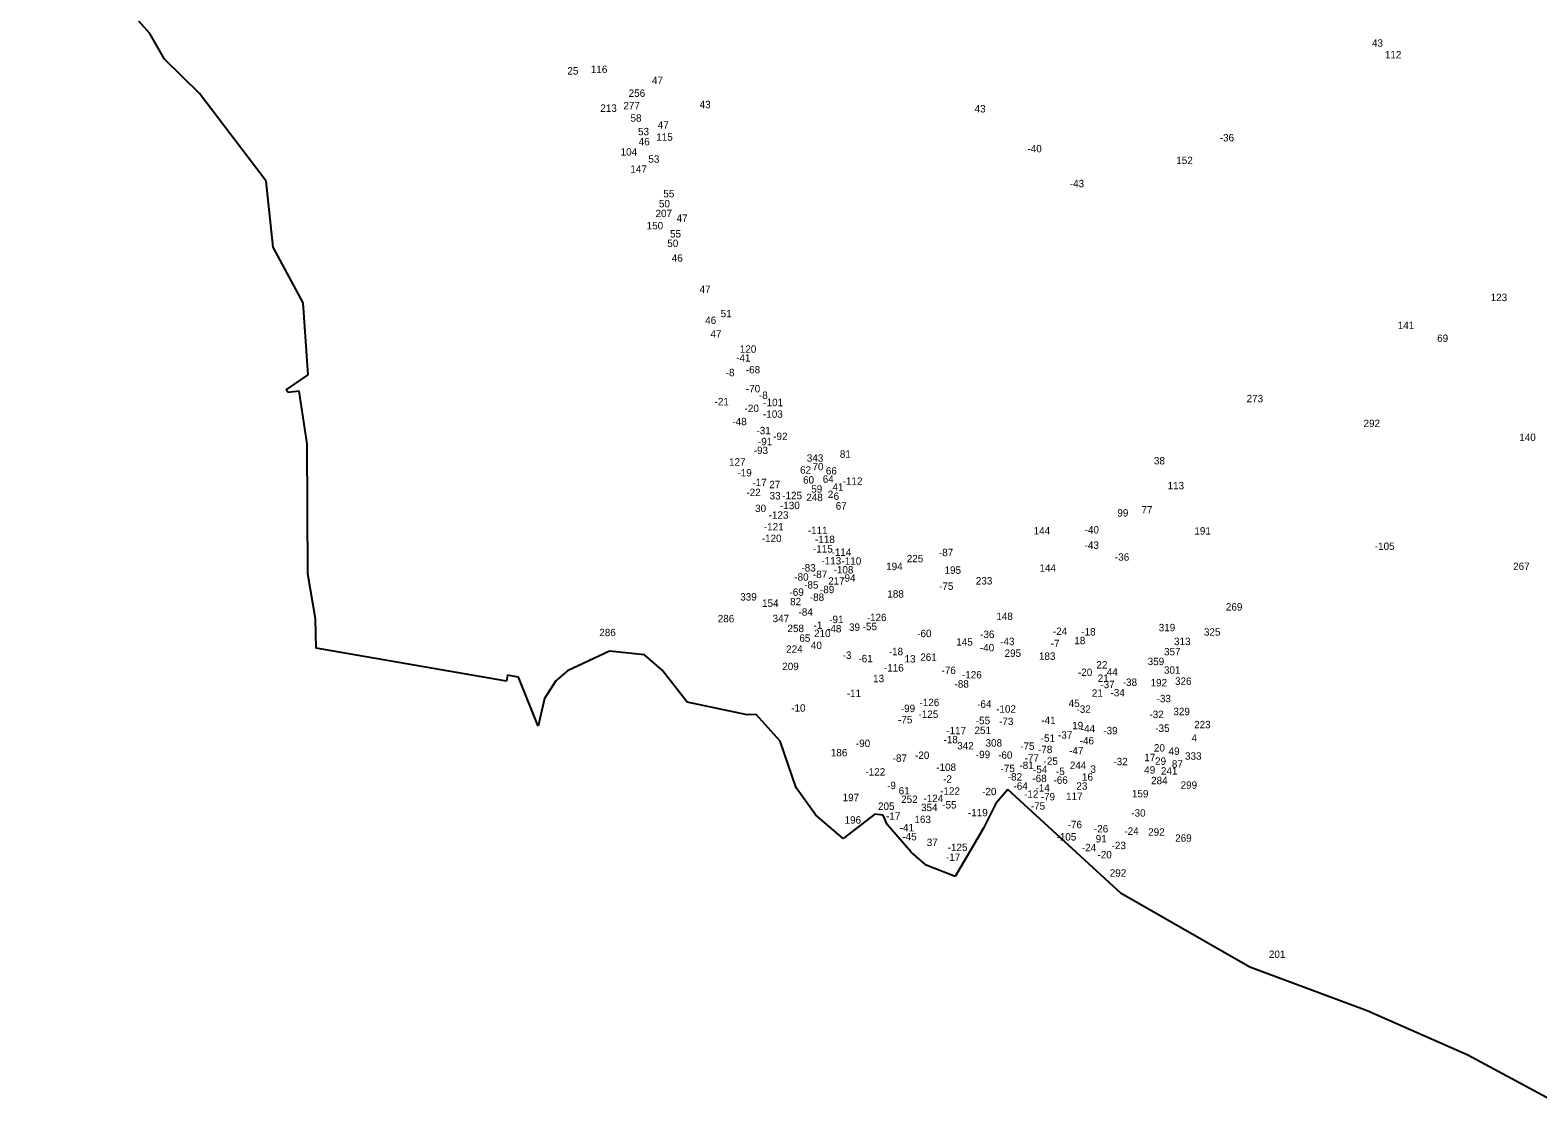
# Model space of a CAD drawing. Extents: x -780116 to -776974, y -980293 to -977147.
# Drawn here: x -779931 to -778640, y -979637 to -978721 of the extents above; entities that cross this region are included whole.
import ezdxf

# ---------------------------------------------------------------- set-up
doc = ezdxf.new("R2010")
doc.units = 0
doc.layers.add('Vrstva 15', color=7, linetype='Continuous')
doc.layers.add('Vrstva 24', color=7, linetype='Continuous')

msp = doc.modelspace()

# ---------------------------------------------------------------- linework, layer by layer
at = {"layer": 'Vrstva 15'}
for p, q in [((-779828.23, -978723.7), (-779930.79, -978608.31)), ((-779815.84, -978745.74), (-779828.23, -978723.7)), ((-779785.83, -978775.04), (-779815.84, -978745.74)), ((-779728.72, -978850.24), (-779785.83, -978775.04)), ((-779722.75, -978906.79), (-779728.72, -978850.24)), ((-779696.96, -978954.35), (-779722.75, -978906.79)), ((-779692.81, -979016.06), (-779696.96, -978954.35)), ((-779711.61, -979028.89), (-779692.81, -979016.06)), ((-779710, -979031.29), (-779711.61, -979028.89)), ((-779700.39, -979029.98), (-779710, -979031.29)), ((-779693.61, -979075.28), (-779700.39, -979029.98)), ((-779693.17, -979186.63), (-779693.61, -979075.28)), ((-779686.47, -979225.1), (-779693.17, -979186.63)), ((-779686.03, -979250.32), (-779686.47, -979225.1)), ((-779523.01, -979278.6), (-779686.03, -979250.32)), ((-779434.65, -979252.76), (-779470.71, -979269.6)), ((-779404.79, -979255.97), (-779434.65, -979252.76)), ((-779389.56, -979269.01), (-779404.79, -979255.97)), ((-779522.13, -979273.35), (-779523.01, -979278.6)), ((-779512.81, -979275.1), (-779522.13, -979273.35)), ((-779495.84, -979316.97), (-779512.81, -979275.1)), ((-779480.69, -979278.27), (-779490.52, -979293.36)), ((-779470.71, -979269.6), (-779480.69, -979278.27)), ((-779368.37, -979296.48), (-779389.56, -979269.01)), ((-779490.52, -979293.36), (-779495.84, -979316.97)), ((-779317.01, -979307.2), (-779368.37, -979296.48)), ((-779309.07, -979306.98), (-779317.01, -979307.2)), ((-779288.6, -979329.86), (-779309.07, -979306.98)), ((-779274.84, -979370.01), (-779288.6, -979329.86)), ((-779258.09, -979393.18), (-779274.84, -979370.01)), ((-779093.81, -979371.44), (-779103.95, -979383.43)), ((-778996.64, -979460.5), (-779093.81, -979371.44)), ((-779234.77, -979413.16), (-779258.09, -979393.18)), ((-779207.6, -979392.31), (-779234.77, -979413.16)), ((-779200.39, -979393.19), (-779207.6, -979392.31)), ((-779197.03, -979401.42), (-779200.39, -979393.19)), ((-779103.95, -979383.43), (-779114.58, -979404.42)), ((-779176.56, -979424.89), (-779197.03, -979401.42)), ((-779114.58, -979404.42), (-779138.91, -979445.95)), ((-779163.68, -979436.18), (-779176.56, -979424.89)), ((-779138.91, -979445.95), (-779163.68, -979436.18)), ((-778886.64, -979523.46), (-778996.64, -979460.5)), ((-778786.11, -979560.92), (-778886.64, -979523.46)), ((-778699.86, -979598.82), (-778786.11, -979560.92)), ((-778628.77, -979637.15), (-778699.86, -979598.82))]:
    msp.add_line(p, q, dxfattribs=at)

# ---------------------------------------------------------------- texts
at = {"layer": 'Vrstva 24'}
for s, p in [('43', (-778781.975, -978735.034)), ('112', (-778770.959, -978744.984)), ('25', (-779470.845, -978758.864)), ('116', (-779450.759, -978757.574)), ('47', (-779398.449, -978767.024)), ('256', (-779418.393, -978778.004)), ('213', (-779442.651, -978790.824)), ('277', (-779422.902, -978788.664)), ('43', (-779357.625, -978787.724)), ('43', (-779122.195, -978791.344)), ('58', (-779416.785, -978799.254)), ('47', (-779393.489, -978805.224)), ('53', (-779410.375, -978810.914)), ('46', (-779409.775, -978819.514)), ('115', (-779394.749, -978815.594)), ('-36', (-778912.299, -978816.154)), ('104', (-779425.245, -978828.304)), ('-40', (-779076.943, -978825.494)), ('147', (-779416.885, -978843.034)), ('53', (-779401.485, -978834.394)), ('152', (-778949.521, -978835.584)), ('-43', (-779040.678, -978855.384)), ('55', (-779388.695, -978864.074)), ('207', (-779395.393, -978881.034)), ('50', (-779392.48, -978872.664)), ('150', (-779402.956, -978891.474)), ('47', (-779377.319, -978885.054)), ('50', (-779385.28, -978906.634)), ('55', (-779382.975, -978898.464)), ('46', (-779381.505, -978919.244)), ('47', (-779357.649, -978946.004)), ('123', (-778680.361, -978952.954)), ('46', (-779352.865, -978972.534)), ('51', (-779339.633, -978966.784)), ('47', (-779348.319, -978984.204)), ('141', (-778759.908, -978976.864)), ('69', (-778726.155, -978987.924)), ('120', (-779323.226, -978997.184)), ('-41', (-779326.326, -979004.764)), ('-8', (-779335.301, -979017.294)), ('-68', (-779318.069, -979014.804)), ('-70', (-779317.998, -979031.134)), ('-8', (-779306.811, -979036.744)), ('273', (-778889.327, -979039.604)), ('-21', (-779344.827, -979042.214)), ('-20', (-779319.133, -979047.974)), ('-101', (-779303.097, -979042.944)), ('-48', (-779329.558, -979059.294)), ('-103', (-779303.349, -979052.884)), ('292', (-778789.203, -979060.824)), ('-31', (-779308.987, -979066.984)), ('-91', (-779307.667, -979076.394)), ('-92', (-779294.619, -979071.944)), ('140', (-778655.885, -979072.844)), ('-93', (-779311.299, -979083.964)), ('343', (-779265.843, -979090.544)), ('81', (-779237.543, -979087.164)), ('127', (-779332.446, -979093.884)), ('-19', (-779325.237, -979103.154)), ('62', (-779271.625, -979100.744)), ('70', (-779261.005, -979097.914)), ('66', (-779249.545, -979101.464)), ('38', (-778968.685, -979092.834)), ('-17', (-779312.441, -979111.464)), ('27', (-779297.96, -979113.224)), ('60', (-779269.05, -979109.284)), ('59', (-779262.075, -979117.084)), ('64', (-779252.235, -979108.564)), ('41', (-779243.882, -979115.354)), ('-112', (-779235.153, -979110.304)), ('113', (-778956.979, -979114.154)), ('-22', (-779317.569, -979119.924)), ('33', (-779297.715, -979122.844)), ('-125', (-779286.895, -979122.654)), ('248', (-779266.303, -979124.284)), ('2', (-779247.937, -979121.694)), ('-6', (-779245.761, -979123.204)), ('30', (-779310.13, -979133.644)), ('-123', (-779298.525, -979139.314)), ('-130', (-779288.819, -979131.154)), ('67', (-779241.11, -979131.514)), ('99', (-778999.985, -979137.494)), ('77', (-778979.344, -979134.864)), ('-121', (-779302.643, -979149.434)), ('-111', (-779264.991, -979152.494)), ('144', (-779071.64, -979152.794)), ('-40', (-779027.983, -979152.034)), ('191', (-778934.019, -979152.924)), ('-120', (-779304.429, -979159.344)), ('-115', (-779260.573, -979168.354)), ('-118', (-779258.823, -979160.194)), ('-43', (-779028.008, -979165.154)), ('-105', (-778779.579, -979166.074)), ('-113', (-779253.353, -979178.554)), ('-114', (-779244.693, -979171.194)), ('-110', (-779236.167, -979178.744)), ('225', (-779180.283, -979176.664)), ('-87', (-779152.763, -979171.414)), ('-36', (-779002.069, -979175.344)), ('-80', (-779276.563, -979192.424)), ('-83', (-779270.469, -979184.594)), ('-87', (-779260.623, -979190.164)), ('-108', (-779242.909, -979186.274)), ('-94', (-779236.399, -979193.264)), ('194', (-779197.921, -979183.404)), ('195', (-779147.941, -979186.534)), ('144', (-779066.66, -979184.734)), ('267', (-778661.128, -979183.324)), ('-69', (-779280.669, -979205.394)), ('-85', (-779268.139, -979199.204)), ('-89', (-779254.579, -979203.144)), ('217', (-779247.546, -979195.804)), ('188', (-779196.911, -979206.924)), ('-75', (-779152.623, -979200.274)), ('233', (-779121.153, -979195.704)), ('339', (-779322.853, -979209.454)), ('154', (-779304.171, -979214.854)), ('82', (-779280.175, -979213.514)), ('-88', (-779263.259, -979209.764)), ('269', (-778907.063, -979218.064)), ('286', (-779342.113, -979228.084)), ('347', (-779295.117, -979227.964)), ('-84', (-779272.959, -979222.414)), ('-91', (-779246.667, -979228.784)), ('-126', (-779214.545, -979227.064)), ('148', (-779103.56, -979226.094)), ('286', (-779443.533, -979239.954)), ('258', (-779282.393, -979236.474)), ('65', (-779272.245, -979244.754)), ('-1', (-779260.069, -979233.764)), ('210', (-779259.666, -979240.704)), ('-48', (-779248.478, -979236.734)), ('39', (-779229.745, -979235.394)), ('-55', (-779218.029, -979234.824)), ('-60', (-779171.363, -979240.804)), ('-36', (-779117.469, -979241.524)), ('-24', (-779055.119, -979238.904)), ('-18', (-779030.867, -979239.414)), ('319', (-778964.541, -979235.744)), ('325', (-778925.843, -979239.524)), ('224', (-779283.553, -979254.204)), ('40', (-779262.379, -979250.974)), ('-18', (-779195.667, -979256.254)), ('145', (-779137.92, -979248.064)), ('-40', (-779117.673, -979252.984)), ('-43', (-779100.278, -979247.664)), ('295', (-779096.533, -979257.664)), ('-7', (-779057.075, -979249.324)), ('18', (-779036.813, -979246.854)), ('357', (-778960.018, -979256.384)), ('313', (-778951.471, -979247.624)), ('209', (-779286.868, -979269.034)), ('-3', (-779235.181, -979259.394)), ('-61', (-779221.667, -979262.304)), ('-116', (-779199.823, -979270.244)), ('13', (-779182.183, -979262.504)), ('261', (-779168.701, -979261.084)), ('183', (-779067.141, -979260.224)), ('22', (-779017.935, -979267.694)), ('359', (-778974.013, -979264.754)), ('301', (-778960.085, -979272.114)), ('13', (-779209.073, -979279.404)), ('-76', (-779150.503, -979272.374)), ('-88', (-779139.379, -979284.034)), ('-126', (-779133.015, -979276.194)), ('-20', (-779033.673, -979274.034)), ('21', (-779016.783, -979279.084)), ('-37', (-779014.543, -979284.484)), ('44', (-779009.064, -979273.834)), ('-38', (-778995.359, -979282.584)), ('192', (-778971.551, -979282.964)), ('326', (-778950.603, -979281.634)), ('-11', (-779231.675, -979292.044)), ('21', (-779021.813, -979291.894)), ('-34', (-779005.869, -979291.474)), ('-33', (-778966.369, -979296.574)), ('-10', (-779279.211, -979304.584)), ('-99', (-779185.379, -979305.024)), ('-125', (-779170.265, -979309.964)), ('-126', (-779169.385, -979299.904)), ('-64', (-779120.019, -979301.304)), ('-102', (-779103.789, -979305.474)), ('45', (-779041.665, -979300.644)), ('-32', (-779034.999, -979305.614)), ('-32', (-778972.489, -979310.134)), ('329', (-778952.033, -979307.644)), ('-75', (-779187.733, -979314.644)), ('251', (-779122.281, -979323.754)), ('-55', (-779121.189, -979315.374)), ('-73', (-779101.243, -979316.114)), ('-41', (-779065.096, -979315.244)), ('19', (-779038.683, -979319.674)), ('-44', (-779031.218, -979322.304)), ('-35', (-778967.529, -979321.944)), ('223', (-778934.243, -979318.844)), ('-90', (-779223.823, -979334.974)), ('-18', (-779148.817, -979331.704)), ('-117', (-779146.417, -979323.974)), ('308', (-779112.837, -979334.544)), ('-51', (-779065.547, -979330.454)), ('-37', (-779050.763, -979327.774)), ('-46', (-779032.229, -979332.654)), ('-39', (-779011.989, -979323.984)), ('4', (-778936.447, -979330.374)), ('186', (-779245.301, -979342.894)), ('-87', (-779192.323, -979347.604)), ('-20', (-779173.183, -979345.124)), ('342', (-779137.083, -979336.984)), ('-99', (-779121.109, -979344.464)), ('-60', (-779102.073, -979344.974)), ('-75', (-779083.193, -979337.314)), ('-77', (-779079.348, -979347.514)), ('-78', (-779067.883, -979340.144)), ('-47', (-779041.293, -979341.254)), ('17', (-778976.898, -979347.034)), ('20', (-778968.68, -979338.794)), ('49', (-778956.135, -979341.634)), ('333', (-778942.053, -979345.774)), ('-122', (-779215.665, -979359.394)), ('-108', (-779155.069, -979355.404)), ('-75', (-779099.943, -979356.404)), ('-81', (-779083.827, -979353.774)), ('-54', (-779072.159, -979357.274)), ('-25', (-779063.139, -979350.134)), ('-5', (-779052.531, -979358.954)), ('244', (-779040.692, -979353.734)), ('3', (-779023.007, -979356.964)), ('-32', (-779003.379, -979350.514)), ('49', (-778976.975, -979357.674)), ('29', (-778967.695, -979350.164)), ('241', (-778962.64, -979358.544)), ('87', (-778953.29, -979352.594)), ('-9', (-779197.081, -979370.974)), ('-2', (-779149.141, -979365.434)), ('-82', (-779093.799, -979363.614)), ('-64', (-779088.929, -979371.484)), ('-68', (-779072.739, -979364.944)), ('-14', (-779070.057, -979373.094)), ('-66', (-779054.669, -979366.394)), ('23', (-779035.075, -979371.464)), ('16', (-779030.273, -979363.734)), ('284', (-778971.083, -979366.774)), ('299', (-778945.833, -979370.654)), ('197', (-779235.235, -979381.314)), ('61', (-779187.223, -979375.574)), ('252', (-779185.103, -979382.824)), ('-124', (-779165.985, -979382.044)), ('-122', (-779151.675, -979375.814)), ('-55', (-779149.909, -979387.594)), ('-20', (-779115.783, -979376.164)), ('-12', (-779079.827, -979378.394)), ('-79', (-779065.583, -979380.624)), ('117', (-779043.903, -979380.284)), ('159', (-778987.491, -979378.024)), ('196', (-779233.531, -979400.544)), ('205', (-779204.907, -979388.764)), ('-17', (-779198.021, -979397.204)), ('163', (-779173.691, -979400.084)), ('354', (-779168.073, -979389.824)), ('-119', (-779127.883, -979394.234)), ('-75', (-779074.083, -979388.624)), ('-30', (-778988.053, -979394.534)), ('-41', (-779186.326, -979407.114)), ('-76', (-779042.533, -979404.454)), ('-26', (-779020.069, -979408.094)), ('-24', (-778993.989, -979410.134)), ('292', (-778973.593, -979410.864)), ('-45', (-779184.058, -979414.824)), ('37', (-779163.17, -979419.764)), ('-125', (-779145.255, -979424.024)), ('-105', (-779052.069, -979415.014)), ('-24', (-779030.349, -979424.204)), ('91', (-779018.533, -979416.674)), ('-23', (-779004.919, -979422.374)), ('269', (-778950.483, -979416.024)), ('-17', (-779146.731, -979432.484)), ('-20', (-779016.983, -979430.244)), ('292', (-779006.493, -979445.944)), ('201', (-778870.265, -979515.604))]:
    msp.add_text(s, height=6.336, dxfattribs=at).set_placement(p)

doc.saveas('drawing.dxf')
